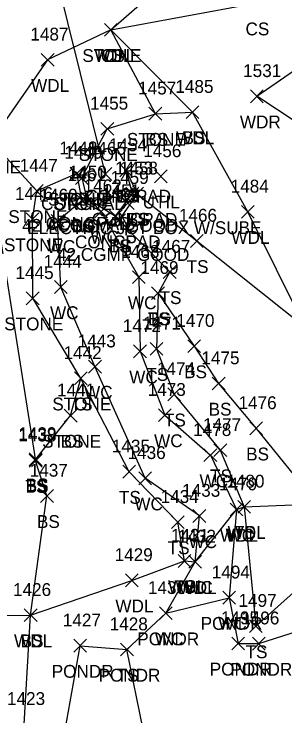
# Model space of a CAD drawing. Extents: x 49137 to 50946, y 9590 to 10709.
# Drawn here: x 50135.2 to 50177.5, y 9888.9 to 9998.3 of the extents above; entities that cross this region are included whole.
import ezdxf

# ---------------------------------------------------------------- set-up
doc = ezdxf.new("R2010")
doc.units = 0
for name, color, linetype in [('D_A', 7, 'Continuous'), ('D_C', 7, 'Continuous'), ('D_I', 7, 'Continuous'), ('D_TIC', 7, 'Continuous'), ('DCP', 7, 'Continuous'), ('L_A', 7, 'Continuous'), ('L_I', 7, 'Continuous'), ('L_TIC', 7, 'Continuous'), ('LASF', 7, 'Continuous'), ('LAWA', 7, 'Continuous'), ('LAWE', 7, 'Continuous'), ('LELB', 7, 'Continuous'), ('LS', 7, 'Continuous'), ('U_A', 7, 'Continuous'), ('U_C', 7, 'Continuous'), ('U_I', 7, 'Continuous'), ('UDEFAULT', 7, 'Continuous')]:
    doc.layers.add(name, color=color, linetype=linetype)

msp = doc.modelspace()

# ---------------------------------------------------------------- linework, layer by layer
at = {"layer": 'D_TIC'}
for points in [[(50148.42, 9972.37), (50150.42, 9974.37)], [(50150.42, 9972.37), (50148.42, 9974.37)], [(50151.93, 9967.83), (50153.93, 9969.83)], [(50153.93, 9967.83), (50151.93, 9969.83)]]:
    msp.add_lwpolyline(points, dxfattribs=at)
at = {"layer": 'DCP'}
msp.add_lwpolyline([(50149.42, 9973.37), (49988.85, 10619.09)], dxfattribs=at)
at = {"layer": 'L_TIC'}
for points in [[(50149.28, 9994.84), (50151.28, 9996.84)], [(50151.28, 9994.84), (50149.28, 9996.84)], [(50149.28, 9994.84), (50151.28, 9996.84)], [(50151.28, 9994.84), (50149.28, 9996.84)], [(50149.28, 9994.84), (50151.28, 9996.84)], [(50151.28, 9994.84), (50149.28, 9996.84)], [(50139.4, 9990.18), (50141.4, 9992.18)], [(50141.4, 9990.18), (50139.4, 9992.18)], [(50172.05, 9984.49), (50174.05, 9986.49)], [(50174.05, 9984.49), (50172.05, 9986.49)], [(50162.03, 9982.02), (50164.03, 9984.02)], [(50164.03, 9982.02), (50162.03, 9984.02)], [(50162.03, 9982.02), (50164.03, 9984.02)], [(50164.03, 9982.02), (50162.03, 9984.02)], [(50156.22, 9981.77), (50158.22, 9983.77)], [(50158.22, 9981.77), (50156.22, 9983.77)], [(50156.22, 9981.77), (50158.22, 9983.77)], [(50158.22, 9981.77), (50156.22, 9983.77)], [(50148.72, 9979.41), (50150.72, 9981.41)], [(50150.72, 9979.41), (50148.72, 9981.41)], [(50143.93, 9972.44), (50145.93, 9974.44)], [(50145.93, 9972.44), (50143.93, 9974.44)], [(50143.93, 9972.44), (50145.93, 9974.44)], [(50145.93, 9972.44), (50143.93, 9974.44)], [(50151.66, 9972.92), (50153.66, 9974.92)], [(50153.66, 9972.92), (50151.66, 9974.92)], [(50151.66, 9972.92), (50153.66, 9974.92)], [(50153.66, 9972.92), (50151.66, 9974.92)], [(50144.73, 9971.76), (50146.73, 9973.76)], [(50146.73, 9971.76), (50144.73, 9973.76)], [(50144.73, 9971.76), (50146.73, 9973.76)], [(50146.73, 9971.76), (50144.73, 9973.76)], [(50137.73, 9969.73), (50139.73, 9971.73)], [(50139.73, 9969.73), (50137.73, 9971.73)], [(50137.73, 9969.73), (50139.73, 9971.73)], [(50139.73, 9969.73), (50137.73, 9971.73)], [(50152.63, 9969.31), (50154.63, 9971.31)], [(50154.63, 9969.31), (50152.63, 9971.31)], [(50153.36, 9969.3), (50155.36, 9971.3)], [(50155.36, 9969.3), (50153.36, 9971.3)], [(50153.36, 9969.3), (50155.36, 9971.3)], [(50155.36, 9969.3), (50153.36, 9971.3)], [(50144.73, 9968.26), (50146.73, 9970.26)], [(50146.73, 9968.26), (50144.73, 9970.26)], [(50144.73, 9968.26), (50146.73, 9970.26)], [(50146.73, 9968.26), (50144.73, 9970.26)], [(50145.47, 9968.67), (50147.47, 9970.67)], [(50147.47, 9968.67), (50145.47, 9970.67)], [(50147.76, 9966.54), (50149.76, 9968.54)], [(50149.76, 9966.54), (50147.76, 9968.54)], [(50150.02, 9965.79), (50152.02, 9967.79)], [(50152.02, 9965.79), (50150.02, 9967.79)], [(50170.66, 9966.48), (50172.66, 9968.48)], [(50172.66, 9966.48), (50170.66, 9968.48)], [(50137.05, 9965.33), (50139.05, 9967.33)], [(50139.05, 9965.33), (50137.05, 9967.33)], [(50140.96, 9965.07), (50142.96, 9967.07)], [(50142.96, 9965.07), (50140.96, 9967.07)], [(50150.54, 9965.17), (50152.54, 9967.17)], [(50152.54, 9965.17), (50150.54, 9967.17)], [(50150.54, 9965.17), (50152.54, 9967.17)], [(50152.54, 9965.17), (50150.54, 9967.17)], [(50162.69, 9961.94), (50164.69, 9963.94)], [(50164.69, 9961.94), (50162.69, 9963.94)], [(50158.46, 9957.1), (50160.46, 9959.1)], [(50160.46, 9957.1), (50158.46, 9959.1)], [(50153.63, 9956.3), (50155.63, 9958.3)], [(50155.63, 9956.3), (50153.63, 9958.3)], [(50141.47, 9954.75), (50143.47, 9956.75)], [(50143.47, 9954.75), (50141.47, 9956.75)], [(50156.64, 9953.79), (50158.64, 9955.79)], [(50158.64, 9953.79), (50156.64, 9955.79)], [(50156.64, 9953.79), (50158.64, 9955.79)], [(50158.64, 9953.79), (50156.64, 9955.79)], [(50137.08, 9953), (50139.08, 9955)], [(50139.08, 9953), (50137.08, 9955)], [(50153.83, 9944.73), (50155.83, 9946.73)], [(50155.83, 9944.73), (50153.83, 9946.73)], [(50156.4, 9945.13), (50158.4, 9947.13)], [(50158.4, 9945.13), (50156.4, 9947.13)], [(50162.27, 9945.54), (50164.27, 9947.54)], [(50164.27, 9945.54), (50162.27, 9947.54)], [(50146.79, 9942.35), (50148.79, 9944.35)], [(50148.79, 9942.35), (50146.79, 9944.35)], [(50144.59, 9940.52), (50146.59, 9942.52)], [(50146.59, 9940.52), (50144.59, 9942.52)], [(50144.59, 9940.52), (50146.59, 9942.52)], [(50146.59, 9940.52), (50144.59, 9942.52)], [(50166.1, 9939.71), (50168.1, 9941.71)], [(50168.1, 9939.71), (50166.1, 9941.71)], [(50159.15, 9938.02), (50161.15, 9940.02)], [(50161.15, 9938.02), (50159.15, 9940.02)], [(50143, 9934.71), (50145, 9936.71)], [(50145, 9934.71), (50143, 9936.71)], [(50143, 9934.71), (50145, 9936.71)], [(50145, 9934.71), (50143, 9936.71)], [(50157.71, 9934.79), (50159.71, 9936.79)], [(50159.71, 9934.79), (50157.71, 9936.79)], [(50171.95, 9932.72), (50173.95, 9934.72)], [(50173.95, 9932.72), (50171.95, 9934.72)], [(50164.81, 9928.53), (50166.81, 9930.53)], [(50166.81, 9928.53), (50164.81, 9930.53)], [(50166.35, 9929.31), (50168.35, 9931.31)], [(50168.35, 9929.31), (50166.35, 9931.31)], [(50137.53, 9927.68), (50139.53, 9929.68)], [(50139.53, 9927.68), (50137.53, 9929.68)], [(50137.53, 9927.68), (50139.53, 9929.68)], [(50139.53, 9927.68), (50137.53, 9929.68)], [(50137.54, 9927.9), (50139.54, 9929.9)], [(50139.54, 9927.9), (50137.54, 9929.9)], [(50152.12, 9925.96), (50154.12, 9927.96)], [(50154.12, 9925.96), (50152.12, 9927.96)], [(50154.63, 9924.94), (50156.63, 9926.94)], [(50156.63, 9924.94), (50154.63, 9926.94)], [(50139.3, 9922.19), (50141.3, 9924.19)], [(50141.3, 9922.19), (50139.3, 9924.19)], [(50168.87, 9920.06), (50170.87, 9922.06)], [(50170.87, 9920.06), (50168.87, 9922.06)], [(50168.87, 9920.06), (50170.87, 9922.06)], [(50170.87, 9920.06), (50168.87, 9922.06)], [(50170.08, 9920.49), (50172.08, 9922.49)], [(50172.08, 9920.49), (50170.08, 9922.49)], [(50170.08, 9920.49), (50172.08, 9922.49)], [(50172.08, 9920.49), (50170.08, 9922.49)], [(50163.09, 9919.06), (50165.09, 9921.06)], [(50165.09, 9919.06), (50163.09, 9921.06)], [(50159.74, 9918.1), (50161.74, 9920.1)], [(50161.74, 9918.1), (50159.74, 9920.1)], [(50160.77, 9912.05), (50162.77, 9914.05)], [(50162.77, 9912.05), (50160.77, 9914.05)], [(50160.77, 9912.05), (50162.77, 9914.05)], [(50162.77, 9912.05), (50160.77, 9914.05)], [(50162.42, 9911.91), (50164.42, 9913.91)], [(50164.42, 9911.91), (50162.42, 9913.91)], [(50162.42, 9911.91), (50164.42, 9913.91)], [(50164.42, 9911.91), (50162.42, 9913.91)], [(50152.56, 9909.03), (50154.56, 9911.03)], [(50154.56, 9909.03), (50152.56, 9911.03)], [(50167.73, 9906.32), (50169.73, 9908.32)], [(50169.73, 9906.32), (50167.73, 9908.32)], [(50167.73, 9906.32), (50169.73, 9908.32)], [(50169.73, 9906.32), (50167.73, 9908.32)], [(50136.75, 9903.59), (50138.75, 9905.59)], [(50138.75, 9903.59), (50136.75, 9905.59)], [(50136.75, 9903.59), (50138.75, 9905.59)], [(50138.75, 9903.59), (50136.75, 9905.59)], [(50157.84, 9903.9), (50159.84, 9905.9)], [(50159.84, 9903.9), (50157.84, 9905.9)], [(50157.84, 9903.9), (50159.84, 9905.9)], [(50159.84, 9903.9), (50157.84, 9905.9)], [(50171.89, 9901.89), (50173.89, 9903.89)], [(50173.89, 9901.89), (50171.89, 9903.89)], [(50144.47, 9898.84), (50146.47, 9900.84)], [(50146.47, 9898.84), (50144.47, 9900.84)], [(50169.14, 9899.19), (50171.14, 9901.19)], [(50171.14, 9899.19), (50169.14, 9901.19)], [(50172.37, 9899.16), (50174.37, 9901.16)], [(50174.37, 9899.16), (50172.37, 9901.16)], [(50151.79, 9898.24), (50153.79, 9900.24)], [(50153.79, 9898.24), (50151.79, 9900.24)], [(50151.79, 9898.24), (50153.79, 9900.24)], [(50153.79, 9898.24), (50151.79, 9900.24)]]:
    msp.add_lwpolyline(points, dxfattribs=at)
at = {"layer": 'LASF'}
for points in [[(50144, 9935.71), (50145.59, 9941.52), (50138.08, 9954), (50138.05, 9966.33), (50138.73, 9970.73), (50144.93, 9973.44), (50145.73, 9972.76), (50149.72, 9980.41), (50157.22, 9982.77), (50150.28, 9995.84), (50164.12, 10007.94)], [(50138.73, 9970.73), (50131.52, 9978.47), (50118.93, 9985.72), (50114.93, 9990.21), (50113.32, 9990.46)]]:
    msp.add_lwpolyline(points, dxfattribs=at)
at = {"layer": 'LAWA'}
for points in [[(50265.38, 9914.66), (50247, 9927.27), (50228.2, 9939.52), (50207.29, 9957.54), (50200.22, 9967.59), (50173.05, 9985.49), (50184.13, 9993.14), (50189.69, 9999.35)], [(50117.09, 9812.03), (50125.19, 9838.2), (50131.44, 9869.96), (50136.76, 9887.6), (50137.75, 9904.59), (50153.56, 9910.03), (50161.77, 9913.05), (50163.42, 9912.91), (50169.87, 9921.06), (50171.08, 9921.49), (50182.45, 9921.95), (50191.92, 9928.44), (50180.6, 9949.5), (50171.66, 9967.48), (50163.03, 9983.02), (50150.28, 9995.84), (50140.4, 9991.18), (50131.52, 9978.47)]]:
    msp.add_lwpolyline(points, dxfattribs=at)
at = {"layer": 'LAWE'}
for points in [[(50158.84, 9904.9), (50163.42, 9912.91), (50164.09, 9920.06), (50155.63, 9925.94), (50147.79, 9943.35), (50142.47, 9955.75), (50141.96, 9966.07), (50145.73, 9969.26), (50148.76, 9967.54), (50154.63, 9957.3), (50154.83, 9945.73), (50158.71, 9935.79), (50165.81, 9929.53), (50169.87, 9921.06), (50168.73, 9907.32)], [(50128.8, 9830.05), (50134.29, 9847.3), (50142.11, 9880.9), (50145.47, 9899.84), (50152.79, 9899.24), (50158.84, 9904.9), (50168.73, 9907.32), (50170.14, 9900.19), (50173.37, 9900.16), (50184.59, 9903.76), (50198.34, 9914.07), (50214.56, 9902.92), (50226.92, 9887.06)]]:
    msp.add_lwpolyline(points, dxfattribs=at)
at = {"layer": 'LELB'}
for points in [[(50150.28, 9995.84), (50172.85, 9999.99), (50191.47, 10010.6)], [(50157.22, 9982.77), (50163.03, 9983.02)], [(50123.33, 9977.29), (50131.36, 9973.37), (50138.53, 9928.68)], [(50144.93, 9973.44), (50145.73, 9969.26)], [(50152.66, 9973.92), (50154.36, 9970.3), (50151.54, 9966.17)], [(50154.36, 9970.3), (50163.69, 9962.94), (50180.6, 9949.5), (50195.14, 9945.74), (50210.23, 9933.85), (50230.67, 9917.13), (50242.1, 9900.88)], [(50151.54, 9966.17), (50159.46, 9958.1), (50157.64, 9954.79), (50157.4, 9946.13), (50160.15, 9939.02), (50167.35, 9930.31), (50171.08, 9921.49), (50172.89, 9902.89), (50185.1, 9913.72), (50189.98, 9922.1), (50206.75, 9919.23), (50216.84, 9906.82), (50233.45, 9889.39)], [(50157.64, 9954.79), (50163.27, 9946.54), (50167.1, 9940.71), (50172.95, 9933.72), (50182.45, 9921.95)], [(50161.77, 9913.05), (50160.74, 9919.1), (50153.12, 9926.96), (50145.59, 9941.52)], [(50131.44, 9869.96), (50121.55, 9894.2), (50128.84, 9904.54), (50137.75, 9904.59), (50140.3, 9923.19), (50138.53, 9928.68), (50138.54, 9928.9), (50144, 9935.71)], [(50134.29, 9847.3), (50150.17, 9869.59), (50154.43, 9869.54), (50157.85, 9874.32), (50152.79, 9899.24)]]:
    msp.add_lwpolyline(points, dxfattribs=at)
at = {"layer": 'LS'}
msp.add_lwpolyline([(50145.73, 9972.76), (50146.47, 9969.67), (50151.02, 9966.79), (50153.63, 9970.31), (50152.66, 9973.92)], dxfattribs=at)
at = {"layer": 'UDEFAULT'}
for points in [[(50157.08, 9972), (50159.08, 9974)], [(50159.08, 9972), (50157.08, 9974)]]:
    msp.add_lwpolyline(points, dxfattribs=at)

# ---------------------------------------------------------------- texts
at = {"layer": 'D_A'}
for p in [(50148.8, 9968.37), (50152.31, 9963.83)]:
    msp.add_text('P', height=2, dxfattribs=at).set_placement(p)
at = {"layer": 'D_C'}
for s, p in [('42 ACCGMP GOOD', (50136.43, 9964.37)), ('42 CGMP GOOD', (50141.87, 9959.83))]:
    msp.add_text(s, height=2, dxfattribs=at).set_placement(p)
at = {"layer": 'D_I'}
for s, p in [('1465', (50146.68, 9976.37)), ('1459', (50150.23, 9971.83))]:
    msp.add_text(s, height=2, dxfattribs=at).set_placement(p)
at = {"layer": 'L_A'}
for s, p in [('CS', (50171.29, 9994.99)), ('STONE', (50145.82, 9990.84)), ('WDL', (50147.7, 9990.84)), ('CS', (50148.72, 9990.84)), ('WDL', (50137.82, 9986.18)), ('WDR', (50170.41, 9980.49)), ('STONE', (50152.77, 9977.77)), ('BS', (50155.66, 9977.77)), ('WDL', (50160.45, 9978.02)), ('BS', (50161.47, 9978.02)), ('STONE', (50145.27, 9975.41)), ('STONE', (50127.06, 9973.47)), ('CONCPAD', (50146.3, 9968.92)), ('BS', (50151.1, 9968.92)), ('CONCPAD', (50139.38, 9967.76)), ('STONE', (50140.47, 9968.44)), ('STONE', (50141.27, 9967.76)), ('BS', (50143.37, 9968.44)), ('STONE', (50134.27, 9965.73)), ('STONE', (50134.27, 9965.73)), ('CONCPAD', (50140.11, 9964.67)), ('CONCPAD', (50147.28, 9965.31)), ('TS', (50152.77, 9965.3)), ('BS', (50152.8, 9965.3)), ('WC', (50144.03, 9964.26)), ('BS', (50144.17, 9964.26)), ('WC', (50147.07, 9962.54)), ('WDL', (50169.08, 9962.48)), ('STONE', (50133.59, 9961.33)), ('CONCPAD', (50144.67, 9961.79)), ('TS', (50149.95, 9961.17)), ('BS', (50149.98, 9961.17)), ('WC', (50140.26, 9961.07)), ('TS', (50162.1, 9957.94)), ('TS', (50157.87, 9953.1)), ('WC', (50152.94, 9952.3)), ('WC', (50140.78, 9950.75)), ('TS', (50156.04, 9949.79)), ('BS', (50156.08, 9949.79)), ('STONE', (50133.63, 9949)), ('BS', (50161.71, 9941.54)), ('WC', (50153.14, 9940.73)), ('TS', (50155.81, 9941.13)), ('WC', (50146.09, 9938.35)), ('STONE', (50141.13, 9936.52)), ('TS', (50144, 9936.52)), ('BS', (50165.54, 9935.71)), ('TS', (50158.56, 9934.02)), ('STONE', (50139.55, 9930.71)), ('BS', (50142.44, 9930.71)), ('WC', (50157.02, 9930.79)), ('BS', (50171.39, 9928.72)), ('TS', (50165.76, 9925.31)), ('WC', (50164.12, 9924.53)), ('TS', (50136.94, 9923.68)), ('BS', (50136.97, 9923.68)), ('BS', (50136.98, 9923.9)), ('TS', (50151.53, 9921.96)), ('WC', (50153.94, 9920.94)), ('BS', (50138.74, 9918.19)), ('WDL', (50168.5, 9916.49)), ('TS', (50169.49, 9916.49)), ('WDL', (50167.29, 9916.06)), ('WC', (50168.18, 9916.06)), ('TS', (50159.15, 9914.1)), ('WC', (50162.4, 9915.06)), ('WDL', (50159.19, 9908.05)), ('TS', (50160.18, 9908.05)), ('WDL', (50160.84, 9907.91)), ('WC', (50161.73, 9907.91)), ('WDL', (50150.98, 9905.03)), ('PONDR', (50164.29, 9902.32)), ('WC', (50167.03, 9902.32)), ('PONDR', (50154.4, 9899.9)), ('WC', (50157.14, 9899.9)), ('WDL', (50135.16, 9899.59)), ('BS', (50136.19, 9899.59)), ('TS', (50171.3, 9897.89)), ('PONDR', (50141.04, 9894.84)), ('PONDR', (50165.71, 9895.19)), ('PONDR', (50168.93, 9895.16)), ('PONDR', (50148.35, 9894.24)), ('TS', (50151.19, 9894.24))]:
    msp.add_text(s, height=2, dxfattribs=at).set_placement(p)
at = {"layer": 'L_I'}
for s, p in [('1487', (50137.71, 9994.18)), ('1531', (50170.92, 9988.49)), ('1457', (50154.53, 9985.77)), ('1457', (50154.53, 9985.77)), ('1485', (50160.34, 9986.02)), ('1485', (50160.34, 9986.02)), ('1455', (50147.03, 9983.41)), ('1448', (50142.23, 9976.44)), ('1448', (50142.23, 9976.44)), ('1454', (50149.97, 9976.92)), ('1454', (50149.97, 9976.92)), ('1449', (50143.03, 9975.76)), ('1449', (50143.03, 9975.76)), ('1447', (50136.04, 9973.73)), ('1447', (50136.04, 9973.73)), ('1453', (50150.94, 9973.31)), ('1458', (50151.67, 9973.3)), ('1458', (50151.67, 9973.3)), ('1461', (50143.55, 9972.26)), ('1461', (50143.55, 9972.26)), ('1450', (50143.69, 9972.67)), ('1462', (50146.02, 9970.54)), ('1484', (50168.97, 9970.48)), ('1446', (50135.3, 9969.33)), ('1460', (50139.13, 9969.07)), ('1463', (50148.8, 9969.17)), ('1463', (50148.8, 9969.17)), ('1451', (50148.9, 9969.79)), ('1466', (50160.89, 9965.94)), ('1468', (50151.89, 9960.3)), ('1467', (50156.72, 9961.1)), ('1444', (50139.78, 9958.75)), ('1445', (50135.39, 9957)), ('1469', (50154.89, 9957.79)), ('1469', (50154.89, 9957.79)), ('1471', (50155.27, 9949.13)), ('1470', (50160.49, 9949.54)), ('1472', (50152.14, 9948.73)), ('1443', (50145.09, 9946.35)), ('1442', (50142.89, 9944.52)), ('1442', (50142.89, 9944.52)), ('1475', (50164.41, 9943.71)), ('1474', (50157.46, 9942.02)), ('1441', (50141.88, 9938.71)), ('1441', (50141.88, 9938.71)), ('1473', (50156.02, 9938.79)), ('1476', (50170.2, 9936.72)), ('1477', (50164.66, 9933.31)), ('1438', (50135.83, 9931.68)), ('1438', (50135.83, 9931.68)), ('1439', (50135.84, 9931.9)), ('1478', (50163.12, 9932.53)), ('1435', (50150.43, 9929.96)), ('1436', (50152.88, 9928.94)), ('1437', (50137.61, 9926.19)), ('1479', (50167.17, 9924.06)), ('1479', (50167.17, 9924.06)), ('1480', (50168.3, 9924.49)), ('1480', (50168.3, 9924.49)), ('1433', (50161.4, 9923.06)), ('1434', (50158.04, 9922.1)), ('1431', (50159.65, 9916.05)), ('1431', (50159.65, 9916.05)), ('1432', (50160.73, 9915.91)), ('1432', (50160.73, 9915.91)), ('1429', (50150.86, 9913.03)), ('1494', (50166.03, 9910.32)), ('1494', (50166.03, 9910.32)), ('1426', (50135, 9907.59)), ('1426', (50135, 9907.59)), ('1430', (50156.06, 9907.9)), ('1430', (50156.06, 9907.9)), ('1497', (50170.2, 9905.89)), ('1495', (50167.45, 9903.19)), ('1496', (50170.62, 9903.16)), ('1427', (50142.78, 9902.84)), ('1428', (50150.09, 9902.24)), ('1428', (50150.09, 9902.24)), ('1423', (50134.06, 9890.6))]:
    msp.add_text(s, height=2, dxfattribs=at).set_placement(p)
at = {"layer": 'U_A'}
msp.add_text('UTIL', height=2, dxfattribs=at).set_placement((50155.25, 9968))
at = {"layer": 'U_C'}
msp.add_text('ELECTRIC JCT BOX W/SUBE', height=2, dxfattribs=at).set_placement((50137.23, 9964))
at = {"layer": 'U_I'}
msp.add_text('1456', height=2, dxfattribs=at).set_placement((50155.33, 9976))

doc.saveas('drawing.dxf')
